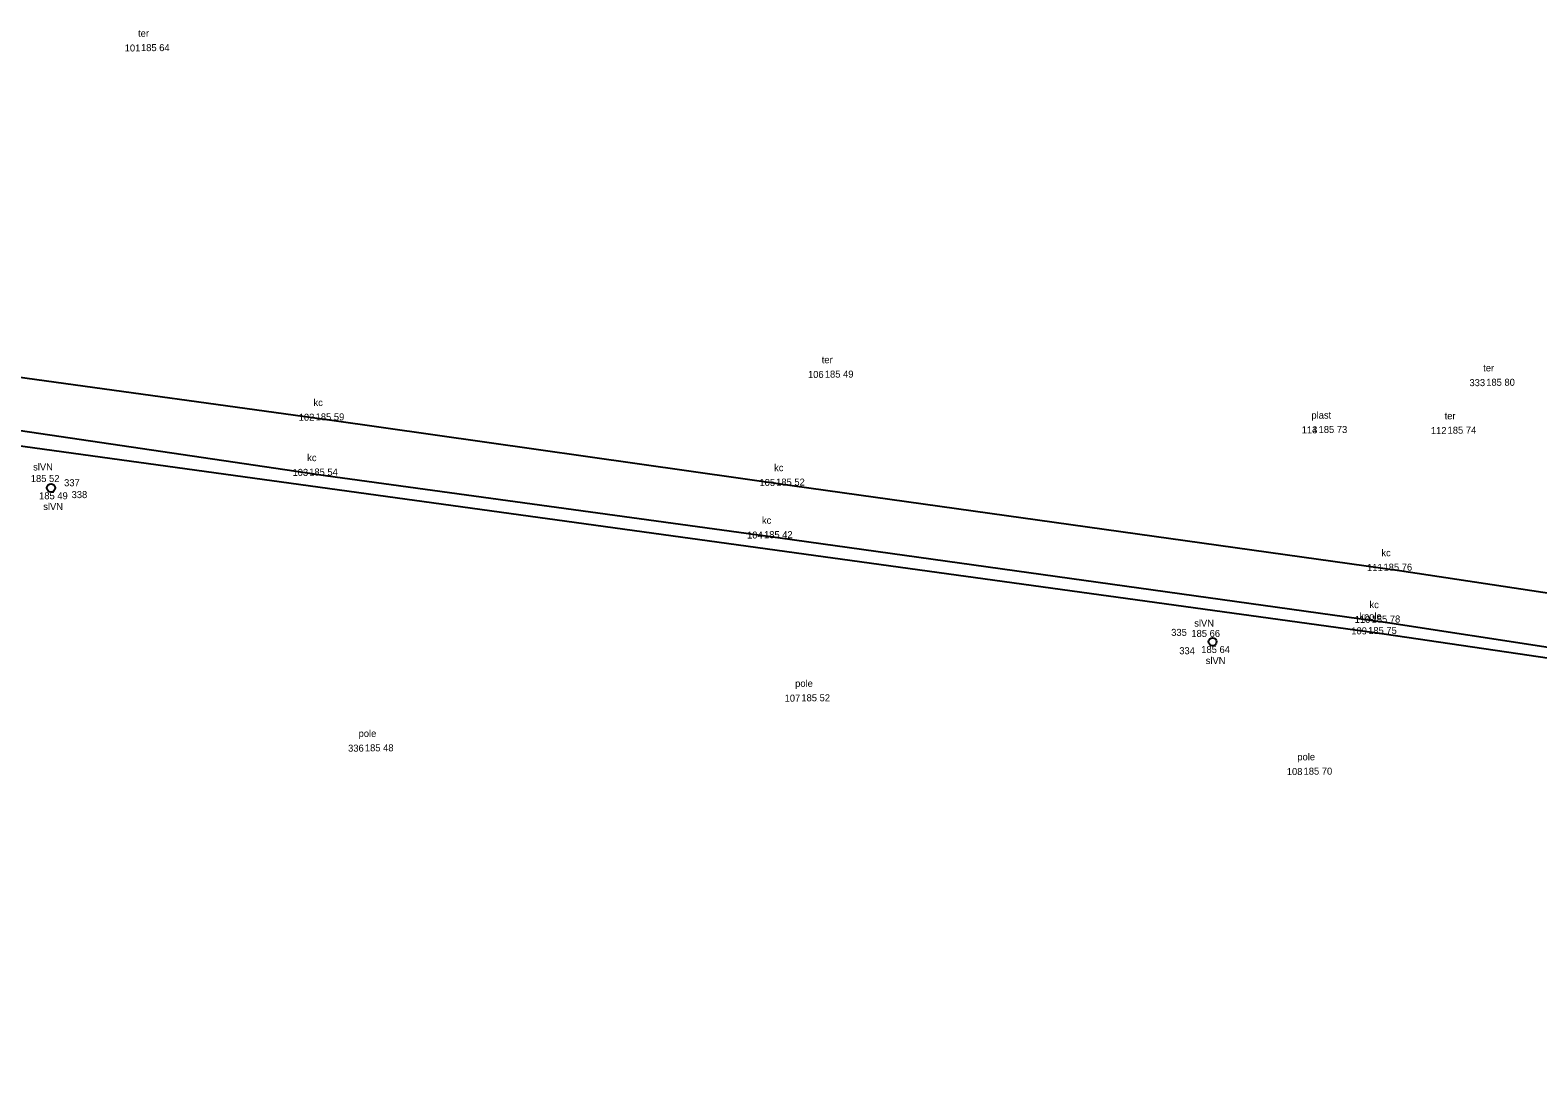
# Model space of a CAD drawing. Extents: x -598527 to -598215, y -1172822 to -1172560.
# Drawn here: x -598454.5 to -598390, y -1172714.5 to -1172669.9 of the extents above; entities that cross this region are included whole.
import ezdxf

# ---------------------------------------------------------------- set-up
doc = ezdxf.new("R2010")
doc.units = 0
for name, color, linetype in [('Body', 7, 'Continuous'), ('Body čísla', 7, 'Continuous'), ('Kody', 7, 'Continuous'), ('PATTERN_CLASS', 7, 'Continuous'), ('Ploty', 7, 'Continuous'), ('Výšky', 7, 'Continuous')]:
    doc.layers.add(name, color=color, linetype=linetype)

msp = doc.modelspace()

# ---------------------------------------------------------------- linework, layer by layer
at = {"layer": 'Body'}
for p, q in [((-598449.1, -1172670.82), (-598449.1, -1172670.82)), ((-598419.83, -1172684.79), (-598419.83, -1172684.79)), ((-598391.51, -1172685.14), (-598391.51, -1172685.14)), ((-598441.63, -1172686.62), (-598441.63, -1172686.62)), ((-598398.69, -1172687.16), (-598398.69, -1172687.16)), ((-598398.69, -1172687.16), (-598398.69, -1172687.16)), ((-598393.16, -1172687.19), (-598393.16, -1172687.19)), ((-598441.9, -1172688.98), (-598441.9, -1172688.98)), ((-598453.82, -1172689.48), (-598453.82, -1172689.48)), ((-598453.47, -1172689.55), (-598453.47, -1172689.55)), ((-598421.91, -1172689.41), (-598421.91, -1172689.41)), ((-598422.43, -1172691.66), (-598422.43, -1172691.66)), ((-598395.91, -1172693.05), (-598395.91, -1172693.05)), ((-598396.57, -1172695.76), (-598396.57, -1172695.76)), ((-598396.42, -1172695.27), (-598396.42, -1172695.27)), ((-598404.08, -1172696.06), (-598404.08, -1172696.06)), ((-598403.75, -1172696.15), (-598403.75, -1172696.15)), ((-598420.83, -1172698.64), (-598420.83, -1172698.64)), ((-598439.52, -1172700.78), (-598439.52, -1172700.78)), ((-598399.33, -1172701.78), (-598399.33, -1172701.78))]:
    msp.add_line(p, q, dxfattribs=at)
at = {"layer": 'PATTERN_CLASS'}
for points in [[(-598492.58, -1172680.02), (-598468.55, -1172682.91), (-598441.63, -1172686.62), (-598421.91, -1172689.41), (-598395.91, -1172693.05), (-598382.12, -1172695.14), (-598364.75, -1172697.57), (-598348.85, -1172699.43), (-598326.25, -1172702.17), (-598291.63, -1172707.83), (-598276.21, -1172710.42), (-598272.67, -1172710.2), (-598270.07, -1172709.11), (-598268.17, -1172706.75)], [(-598504.27, -1172686.48), (-598502.86, -1172683.29), (-598501.21, -1172681.85), (-598498.91, -1172681.7), (-598493.15, -1172682.35), (-598468.61, -1172685.05), (-598441.9, -1172688.98), (-598422.43, -1172691.66), (-598396.42, -1172695.27), (-598382.3, -1172697.44), (-598365.39, -1172699.67), (-598349.07, -1172701.68), (-598326.56, -1172704.69), (-598292, -1172710.32), (-598276.32, -1172712.66), (-598273.75, -1172712.88), (-598270.71, -1172712.27), (-598268.64, -1172711.13), (-598269.17, -1172714.46)]]:
    msp.add_lwpolyline(points, dxfattribs=at)
for centre, radius in [((-598453.645, -1172689.517), 0.178), ((-598403.914, -1172696.101), 0.171)]:
    msp.add_circle(centre, radius, dxfattribs=at)
at = {"layer": 'Ploty'}
for p, q in [((-598469.38, -1172685.74), (-598396.57, -1172695.76)), ((-598396.57, -1172695.76), (-598382.27, -1172697.88))]:
    msp.add_line(p, q, dxfattribs=at)

# ---------------------------------------------------------------- texts
at = {"layer": 'Body čísla'}
for s, p in [('101', (-598450.491, -1172670.843)), ('106', (-598421.237, -1172684.813)), ('333', (-598392.917, -1172685.163)), ('102', (-598443.041, -1172686.643)), ('114', (-598400.104, -1172687.183)), ('113', (-598400.097, -1172687.183)), ('112', (-598394.571, -1172687.213)), ('337', (-598453.086, -1172689.446)), ('103', (-598443.307, -1172689.003)), ('105', (-598423.315, -1172689.433)), ('338', (-598452.764, -1172689.954)), ('104', (-598423.844, -1172691.683)), ('111', (-598397.301, -1172693.073)), ('110', (-598397.83, -1172695.293)), ('335', (-598405.687, -1172695.849)), ('109', (-598397.976, -1172695.783)), ('334', (-598405.341, -1172696.634)), ('107', (-598422.238, -1172698.663)), ('336', (-598440.927, -1172700.803)), ('108', (-598400.738, -1172701.803))]:
    msp.add_text(s, height=0.3, dxfattribs=at).set_placement(p)
at = {"layer": 'Kody'}
for s, p in [('ter', (-598449.919, -1172670.213)), ('ter', (-598420.649, -1172684.183)), ('ter', (-598392.329, -1172684.533)), ('kc', (-598442.408, -1172686.013)), ('plast', (-598399.684, -1172686.553)), ('plast', (-598399.684, -1172686.553)), ('ter', (-598393.979, -1172686.583)), ('slVN', (-598454.411, -1172688.771)), ('kc', (-598442.678, -1172688.373)), ('kc', (-598422.688, -1172688.803)), ('kc', (-598423.208, -1172691.053)), ('kc', (-598396.688, -1172692.443)), ('kc', (-598397.198, -1172694.663)), ('kpole', (-598397.634, -1172695.153)), ('slVN', (-598404.701, -1172695.453)), ('pole', (-598421.787, -1172698.033)), ('pole', (-598440.477, -1172700.173)), ('pole', (-598400.287, -1172701.173))]:
    msp.add_text(s, height=0.3, dxfattribs=at).set_placement(p)
at = {"layer": 'PATTERN_CLASS'}
for p in [(-598453.978, -1172690.464), (-598404.21, -1172697.055)]:
    msp.add_text('slVN', height=0.3, dxfattribs=at).set_placement(p)
at = {"layer": 'Výšky'}
for s, p in [('185 64', (-598449.794, -1172670.828)), ('185 49', (-598420.517, -1172684.798)), ('185 80', (-598392.2, -1172685.148)), ('185 59', (-598442.317, -1172686.628)), ('185 73', (-598399.377, -1172687.168)), ('185 73', (-598399.377, -1172687.168)), ('185 74', (-598393.854, -1172687.198)), ('185 52', (-598454.511, -1172689.266)), ('185 54', (-598442.594, -1172688.988)), ('185 52', (-598422.601, -1172689.418)), ('185 49', (-598454.157, -1172690.004)), ('185 42', (-598423.121, -1172691.668)), ('185 76', (-598396.598, -1172693.058)), ('185 78', (-598397.108, -1172695.278)), ('185 66', (-598404.824, -1172695.894)), ('185 75', (-598397.256, -1172695.768)), ('185 64', (-598404.4, -1172696.582)), ('185 52', (-598421.521, -1172698.648)), ('185 48', (-598440.208, -1172700.788)), ('185 70', (-598400.02, -1172701.788))]:
    msp.add_text(s, height=0.3, dxfattribs=at).set_placement(p)

doc.saveas('drawing.dxf')
